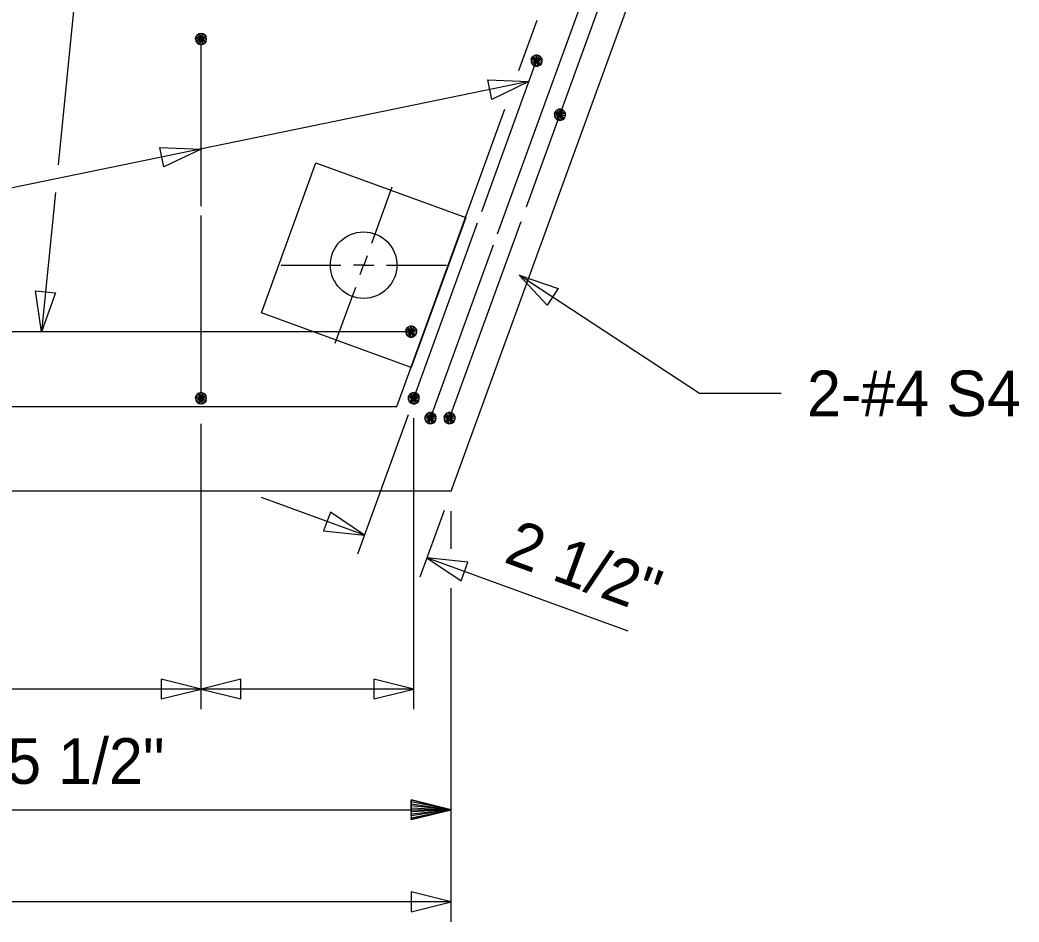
# Model space of a CAD drawing. Extents: x -408 to -23, y -15 to 117.
# Drawn here: x -81.61 to -78.479, y 76.669 to 79.494 of the extents above; entities that cross this region are included whole.
import ezdxf

# ---------------------------------------------------------------- set-up
doc = ezdxf.new("R2010")
doc.units = 0
for name, color, linetype in [('Arrowhead Terminators CELL', 7, 'Continuous'), ('Dimension Lines', 7, 'Continuous'), ('Rebar Lines', 7, 'Continuous'), ('Sup Concrete Girder Lines', 7, 'Continuous'), ('Sup Cored Slab Unit', 7, 'Continuous'), ('Text', 7, 'Continuous')]:
    doc.layers.add(name, color=color, linetype=linetype)

msp = doc.modelspace()

# ---------------------------------------------------------------- linework, layer by layer
at = {"layer": 'Arrowhead Terminators CELL'}
for points in [[(-80.0147, 79.3014), (-80.1308, 79.2456), (-80.1434, 79.3068)], [(-81.0423, 79.09), (-81.1584, 79.0342), (-81.171, 79.0954)], [(-80.0452, 78.6952), (-79.9236, 78.6528), (-79.9578, 78.6006)], [(-81.5418, 78.5181), (-81.5605, 78.6456), (-81.4983, 78.6394)], [(-80.53, 77.8807), (-80.6368, 77.9528), (-80.6582, 77.8941)], [(-80.3343, 77.8094), (-80.2275, 77.7373), (-80.2062, 77.796)], [(-81.0423, 77.399), (-81.1673, 77.4302), (-81.1673, 77.3677)], [(-81.0423, 77.399), (-80.9173, 77.3677), (-80.9173, 77.4302)], [(-80.3756, 77.399), (-80.5006, 77.4302), (-80.5006, 77.3677)], [(-80.2584, 76.7323), (-80.3834, 76.7635), (-80.3834, 76.701)]]:
    msp.add_lwpolyline(points, close=True, dxfattribs=at)
at = {"layer": 'Dimension Lines'}
for p, q in [((-81.3803, 80.1374), (-81.4897, 79.0404)), ((-81.4984, 78.9536), (-81.5418, 78.5181)), ((-80.5076, 78.7953), (-80.4435, 78.9715)), ((-80.7917, 78.7267), (-80.6041, 78.7267)), ((-80.461, 78.7267), (-80.2735, 78.7267)), ((-80.6217, 78.4819), (-80.5575, 78.658)), ((-80.5515, 77.8219), (-80.3927, 78.2583)), ((-80.3756, 77.3359), (-80.3756, 78.2472)), ((-81.0423, 77.3359), (-81.0423, 78.2296)), ((-80.53, 77.8807), (-80.8533, 77.9984)), ((-80.3557, 77.7507), (-80.2798, 77.9594)), ((-80.2584, 77.838), (-80.2584, 77.9556)), ((-79.7043, 77.5801), (-80.3343, 77.8094)), ((-80.2584, 76.6693), (-80.2584, 77.7144)), ((-81.0423, 77.399), (-82.0423, 77.399)), ((-80.3756, 77.399), (-81.0423, 77.399)), ((-82.7168, 77.021), (-80.2584, 77.021)), ((-80.2584, 76.7323), (-83.2584, 76.7323))]:
    msp.add_line(p, q, dxfattribs=at)
for points in [[(-80.0147, 79.3014), (-84.0844, 78.464), (-84.1864, 78.464)], [(-80.5217, 78.7561), (-80.5326, 78.7267), (-80.501, 78.7266)], [(-80.5436, 78.697), (-80.5329, 78.7265), (-80.5643, 78.7265)], [(-79.2243, 78.3249), (-79.4803, 78.3249), (-80.0452, 78.6952)], [(-80.3834, 77.021), (-80.3834, 77.0273), (-80.2584, 77.021), (-80.3834, 77.0335), (-80.3834, 77.0398), (-80.2584, 77.021), (-80.3834, 77.046), (-80.3834, 77.0523), (-80.2584, 77.021), (-80.3834, 76.9898), (-80.3834, 76.996), (-80.2584, 77.021), (-80.3834, 77.0023), (-80.3834, 77.0085), (-80.2584, 77.021), (-80.3834, 77.0148), (-80.3834, 77.0523), (-80.3834, 76.9898), (-80.2584, 77.021), (-80.3834, 77.0523)]]:
    msp.add_lwpolyline(points, dxfattribs=at)
at = {"layer": 'Rebar Lines'}
for p, q in [((-80.0227, 78.9091), (-79.7198, 79.7412)), ((-80.1134, 78.8243), (-79.7978, 79.6917)), ((-80.0464, 79.3358), (-79.9887, 79.4942)), ((-81.0423, 78.9233), (-81.0423, 79.4347)), ((-81.0423, 78.9115), (-81.0423, 79.4347)), ((-80.1629, 78.8943), (-79.9908, 79.3669)), ((-80.4293, 78.2837), (-80.0902, 79.2153)), ((-81.0423, 78.3097), (-81.0423, 78.8824)), ((-80.3756, 78.3097), (-80.1758, 78.8586)), ((-80.2636, 78.2472), (-80.0394, 78.8634)), ((-80.3234, 78.2472), (-80.1257, 78.7904)), ((-80.3836, 78.5181), (-83.0711, 78.5181)), ((-81.7061, 78.2837), (-80.4293, 78.2837))]:
    msp.add_line(p, q, dxfattribs=at)
for points in [[(-81.0247, 79.4347), (-81.026, 79.4415), (-81.0298, 79.4472), (-81.0355, 79.451), (-81.0423, 79.4523), (-81.049, 79.451), (-81.0547, 79.4472), (-81.0585, 79.4415), (-81.0599, 79.4347), (-81.0585, 79.428), (-81.0547, 79.4223), (-81.0491, 79.4184), (-81.0423, 79.4171), (-81.0355, 79.4184), (-81.0298, 79.4222), (-81.026, 79.428), (-81.0247, 79.4347), (-81.0423, 79.4347), (-81.0599, 79.4347), (-81.0585, 79.4415), (-81.0423, 79.4347), (-81.0547, 79.4472), (-81.049, 79.451), (-81.0423, 79.4347), (-81.0423, 79.4523), (-81.0355, 79.451), (-81.0423, 79.4347), (-81.0298, 79.4472), (-81.026, 79.4415), (-81.0423, 79.4347), (-81.026, 79.428), (-81.0298, 79.4222), (-81.0423, 79.4347), (-81.0355, 79.4184), (-81.0423, 79.4171), (-81.0423, 79.4347), (-81.0491, 79.4184), (-81.0547, 79.4223), (-81.0423, 79.4347), (-81.0585, 79.428)], [(-79.9735, 79.3639), (-79.9736, 79.3707), (-79.9763, 79.377), (-79.9813, 79.3818), (-79.9878, 79.3843), (-79.9946, 79.3842), (-80.0009, 79.3813), (-80.0057, 79.3765), (-80.0082, 79.37), (-80.008, 79.3632), (-80.0053, 79.3569), (-80.0003, 79.3521), (-79.9939, 79.3496), (-79.987, 79.3497), (-79.9807, 79.3525), (-79.9759, 79.3574), (-79.9735, 79.3639), (-79.9908, 79.3669), (-80.0082, 79.37), (-80.0057, 79.3765), (-79.9908, 79.3669), (-80.0009, 79.3813), (-79.9946, 79.3842), (-79.9908, 79.3669), (-79.9878, 79.3843), (-79.9813, 79.3818), (-79.9908, 79.3669), (-79.9763, 79.377), (-79.9736, 79.3707), (-79.9908, 79.3669), (-79.9759, 79.3574), (-79.9807, 79.3525), (-79.9908, 79.3669), (-79.987, 79.3497), (-79.9939, 79.3496), (-79.9908, 79.3669), (-80.0003, 79.3521), (-80.0053, 79.3569), (-79.9908, 79.3669), (-80.008, 79.3632)], [(-79.9004, 79.1945), (-79.9005, 79.2013), (-79.9033, 79.2077), (-79.9083, 79.2124), (-79.9147, 79.2149), (-79.9216, 79.2148), (-79.9279, 79.212), (-79.9326, 79.207), (-79.9351, 79.2006), (-79.9349, 79.1937), (-79.9322, 79.1874), (-79.9272, 79.1827), (-79.9208, 79.1802), (-79.9139, 79.1803), (-79.9077, 79.1831), (-79.9029, 79.1881), (-79.9004, 79.1945), (-79.9178, 79.1975), (-79.9351, 79.2006), (-79.9326, 79.207), (-79.9178, 79.1975), (-79.9279, 79.212), (-79.9216, 79.2148), (-79.9178, 79.1975), (-79.9147, 79.2149), (-79.9083, 79.2124), (-79.9178, 79.1975), (-79.9033, 79.2077), (-79.9005, 79.2013), (-79.9178, 79.1975), (-79.9029, 79.1881), (-79.9077, 79.1831), (-79.9178, 79.1975), (-79.9139, 79.1803), (-79.9208, 79.1802), (-79.9178, 79.1975), (-79.9272, 79.1827), (-79.9322, 79.1874), (-79.9178, 79.1975), (-79.9349, 79.1937)], [(-80.3663, 78.515), (-80.3664, 78.5219), (-80.3692, 78.5282), (-80.3741, 78.533), (-80.3806, 78.5355), (-80.3874, 78.5354), (-80.3937, 78.5325), (-80.3984, 78.5276), (-80.4009, 78.5212), (-80.4008, 78.5143), (-80.398, 78.508), (-80.3931, 78.5032), (-80.3867, 78.5007), (-80.3798, 78.5009), (-80.3735, 78.5036), (-80.3688, 78.5086), (-80.3663, 78.515), (-80.3836, 78.5181), (-80.4009, 78.5212), (-80.3984, 78.5276), (-80.3836, 78.5181), (-80.3937, 78.5325), (-80.3874, 78.5354), (-80.3836, 78.5181), (-80.3806, 78.5355), (-80.3741, 78.533), (-80.3836, 78.5181), (-80.3692, 78.5282), (-80.3664, 78.5219), (-80.3836, 78.5181), (-80.3688, 78.5086), (-80.3735, 78.5036), (-80.3836, 78.5181), (-80.3798, 78.5009), (-80.3867, 78.5007), (-80.3836, 78.5181), (-80.3931, 78.5032), (-80.398, 78.508), (-80.3836, 78.5181), (-80.4008, 78.5143)], [(-81.0247, 78.3097), (-81.026, 78.3165), (-81.0298, 78.3222), (-81.0355, 78.326), (-81.0423, 78.3273), (-81.049, 78.326), (-81.0547, 78.3222), (-81.0585, 78.3165), (-81.0599, 78.3097), (-81.0585, 78.303), (-81.0547, 78.2973), (-81.0491, 78.2934), (-81.0423, 78.2921), (-81.0355, 78.2934), (-81.0298, 78.2972), (-81.026, 78.303), (-81.0247, 78.3097), (-81.0423, 78.3097), (-81.0599, 78.3097), (-81.0585, 78.3165), (-81.0423, 78.3097), (-81.0547, 78.3222), (-81.049, 78.326), (-81.0423, 78.3097), (-81.0423, 78.3273), (-81.0355, 78.326), (-81.0423, 78.3097), (-81.0298, 78.3222), (-81.026, 78.3165), (-81.0423, 78.3097), (-81.026, 78.303), (-81.0298, 78.2972), (-81.0423, 78.3097), (-81.0355, 78.2934), (-81.0423, 78.2921), (-81.0423, 78.3097), (-81.0491, 78.2934), (-81.0547, 78.2973), (-81.0423, 78.3097), (-81.0585, 78.303)], [(-80.3583, 78.3067), (-80.3584, 78.3135), (-80.3611, 78.3198), (-80.3661, 78.3246), (-80.3725, 78.3271), (-80.3794, 78.327), (-80.3857, 78.3242), (-80.3904, 78.3192), (-80.393, 78.3128), (-80.3928, 78.3059), (-80.39, 78.2996), (-80.3851, 78.2948), (-80.3787, 78.2923), (-80.3718, 78.2925), (-80.3655, 78.2953), (-80.3607, 78.3003), (-80.3583, 78.3067), (-80.3756, 78.3097), (-80.393, 78.3128), (-80.3904, 78.3192), (-80.3756, 78.3097), (-80.3857, 78.3242), (-80.3794, 78.327), (-80.3756, 78.3097), (-80.3725, 78.3271), (-80.3661, 78.3246), (-80.3756, 78.3097), (-80.3611, 78.3198), (-80.3584, 78.3135), (-80.3756, 78.3097), (-80.3607, 78.3003), (-80.3655, 78.2953), (-80.3756, 78.3097), (-80.3718, 78.2925), (-80.3787, 78.2923), (-80.3756, 78.3097), (-80.3851, 78.2948), (-80.39, 78.2996), (-80.3756, 78.3097), (-80.3928, 78.3059)], [(-80.306, 78.2442), (-80.3062, 78.251), (-80.3089, 78.2573), (-80.3139, 78.2621), (-80.3204, 78.2646), (-80.3272, 78.2645), (-80.3335, 78.2617), (-80.3382, 78.2568), (-80.3407, 78.2503), (-80.3406, 78.2435), (-80.3378, 78.2372), (-80.3329, 78.2324), (-80.3265, 78.2299), (-80.3196, 78.23), (-80.3133, 78.2328), (-80.3085, 78.2378), (-80.306, 78.2442), (-80.3234, 78.2472), (-80.3407, 78.2503), (-80.3382, 78.2568), (-80.3234, 78.2472), (-80.3335, 78.2617), (-80.3272, 78.2645), (-80.3234, 78.2472), (-80.3204, 78.2646), (-80.3139, 78.2621), (-80.3234, 78.2472), (-80.3089, 78.2573), (-80.3062, 78.251), (-80.3234, 78.2472), (-80.3085, 78.2378), (-80.3133, 78.2328), (-80.3234, 78.2472), (-80.3196, 78.23), (-80.3265, 78.2299), (-80.3234, 78.2472), (-80.3329, 78.2324), (-80.3378, 78.2372), (-80.3234, 78.2472), (-80.3406, 78.2435)], [(-80.2463, 78.2442), (-80.2464, 78.251), (-80.2492, 78.2573), (-80.2541, 78.2621), (-80.2606, 78.2646), (-80.2674, 78.2645), (-80.2737, 78.2617), (-80.2784, 78.2567), (-80.2809, 78.2503), (-80.2808, 78.2434), (-80.278, 78.2371), (-80.2731, 78.2323), (-80.2667, 78.2298), (-80.2598, 78.23), (-80.2535, 78.2328), (-80.2487, 78.2378), (-80.2463, 78.2442), (-80.2636, 78.2472), (-80.2809, 78.2503), (-80.2784, 78.2567), (-80.2636, 78.2472), (-80.2737, 78.2617), (-80.2674, 78.2645), (-80.2636, 78.2472), (-80.2606, 78.2646), (-80.2541, 78.2621), (-80.2636, 78.2472), (-80.2492, 78.2573), (-80.2464, 78.251), (-80.2636, 78.2472), (-80.2487, 78.2378), (-80.2535, 78.2328), (-80.2636, 78.2472), (-80.2598, 78.23), (-80.2667, 78.2298), (-80.2636, 78.2472), (-80.2731, 78.2323), (-80.278, 78.2371), (-80.2636, 78.2472), (-80.2808, 78.2434)]]:
    msp.add_lwpolyline(points, dxfattribs=at)
at = {"layer": 'Sup Concrete Girder Lines'}
for q in [(-79.1879, 80.9594), (-84.0018, 78.0181)]:
    msp.add_line((-80.2584, 78.0181), q, dxfattribs=at)
msp.add_circle((-80.5329, 78.7265), 0.1042, dxfattribs=at)
at = {"layer": 'Sup Cored Slab Unit'}
msp.add_lwpolyline([(-80.6823, 79.0469), (-80.2125, 78.8759), (-80.3835, 78.406), (-80.8533, 78.577)], close=True, dxfattribs=at)

# ---------------------------------------------------------------- texts
at = {"layer": 'Text'}
for s, p in [('2-#4 S4', (-79.1434, 78.2534)), ('2\'-5 1/2"', (-81.8564, 77.102))]:
    msp.add_text(s, height=0.14302, dxfattribs=at).set_placement(p)
msp.add_text('2 1/2"', height=0.14302, rotation=339.9998, dxfattribs=at).set_placement((-80.0977, 77.7975))

doc.saveas('drawing.dxf')
